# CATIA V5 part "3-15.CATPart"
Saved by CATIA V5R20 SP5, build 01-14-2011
Part number: Part3
Material "Brass": density 8216 kg/m3, Young's modulus 1.31e+11 Pa, Poisson ratio 0.35, thermal expansion 1.67e-05 1/K
Bounding box of the stored display mesh (mm): x -25 to 25, y -25 to 25, z -60 to 50
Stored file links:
  E:\180511232\3-15.CATPart
  C:\Program Files\Dassault Systemes\B20\intel_a\startup\materials\Catalog.CATMaterial
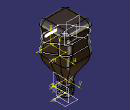
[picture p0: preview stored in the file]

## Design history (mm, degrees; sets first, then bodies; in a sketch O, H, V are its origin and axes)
Set1
  Sketch1 on xy-plane, origin (0, 0, 0), H (1, 0, 0), V (0, 1, 0)
    line L1 (25, 25) -> (25, -25)
    line L2 (25, -25) -> (-25, -25)
    line L3 (-25, -25) -> (-25, 25)
    line L4 (-25, 25) -> (25, 25)
    length L4 = 50
    length L1 = 50
    vertical: L1 V, L3 V
    horizontal: L2 H, L4 H
    equidistance: L1 L3 O, L2 L4 O
  Sketch2 on face of Pad1 from Sketch1.L3, origin (-25, 0, 0), H (0, -1, 0), V (0, 0, 1)
    spline S1 through (-42.1157, 18.4827) (-11.1794, 31.201) (8.2754, 22.6162) (38.5738, 31.201)
  Extrude1: Element1 Sketch2, Lim1 53, Lim2 53
  MultiSel1: CommonCtxFeats ({extract ExtractElem face of Pad1 from Sketch1.L3}; {extract ExtractElem face of Fillet1}; {extract ExtractElem face of Pad1 from Sketch1.L4}; {extract ExtractElem face of Fillet1}; {extract ExtractElem face of Pad1 from Sketch1.L1}; {extract ExtractElem face of Fillet1}; {extract ExtractElem face of Pad1 from Sketch1.L2}; {extract ExtractElem face of Fillet1})
  Sketch3 on face of Pad1 from Sketch1.L1, origin (25, 0, 0), H (0, 1, 0), V (0, 0, 1)
    spline S1 through (-35.6508, 14.5425) (-12.1043, 6.1379) (11.1515, 14.5425) (28.8841, 14.5425)
  Extrude2: Element1 Sketch3, Lim1 65, Lim2 65
  MultiSel2: CommonCtxFeats ({extract ExtractElem face of Pad1 from Sketch1.L1}; {extract ExtractElem face of Fillet1}; {extract ExtractElem face of Pad1 from Sketch1.L2}; {extract ExtractElem face of Fillet1}; {extract ExtractElem face of Pad1 from Sketch1.L3}; {extract ExtractElem face of Fillet1}; {extract ExtractElem face of Pad1 from Sketch1.L4}; {extract ExtractElem face of Fillet1})
  Join1: Elements ({intersect ToIntersect1 {extract ExtractElem face of Fillet1}, ToIntersect2 Extrude1}; {intersect ToIntersect1 {extract ExtractElem face of Pad1 from Sketch1.L4}, ToIntersect2 Extrude1}; {intersect ToIntersect1 {extract ExtractElem face of Fillet1}, ToIntersect2 Extrude1}; {intersect ToIntersect1 {extract ExtractElem face of Pad1 from Sketch1.L1}, ToIntersect2 Extrude1}; {intersect ToIntersect1 {extract ExtractElem face of Fillet1}, ToIntersect2 Extrude1}; {intersect ToIntersect1 {extract ExtractElem face of Pad1 from Sketch1.L2}, ToIntersect2 Extrude1}; {intersect ToIntersect1 {extract ExtractElem face of Fillet1}, ToIntersect2 Extrude1}; {intersect ToIntersect1 {extract ExtractElem face of Pad1 from Sketch1.L3}, ToIntersect2 Extrude1})
  Plane1: type OffsetPt, RefPlane face of Pad1 from Sketch1.L2, RefPoint vertex of MultiSel2
  Circle1: type CtrRad, Start 0, End 180, Center vertex of MultiSel2, Support Plane1, Radius 1, FirstDirection (-1, 0, 0)
  Plane2: type OffsetPt, RefPlane face of Pad1 from Sketch1.L2, RefPoint vertex [face of MultiSel1 | face of MultiSel1]
  Circle2: type CtrRad, Start 0, End 180, Center vertex [face of MultiSel1 | face of MultiSel1], Support Plane2, Radius 1, FirstDirection (-1, 0, 0)
Body1 (main body), material "Brass"
  Pad1: profile Sketch1, direction (0, 0, 1), length 50
  Fillet1: on edge [face of Pad1 from Sketch1.L4 | face of Pad1 from Sketch1.L1]; edge [face of Pad1 from Sketch1.L3 | face of Pad1 from Sketch1.L4]; edge [face of Pad1 from Sketch1.L1 | face of Pad1 from Sketch1.L2]; edge [face of Pad1 from Sketch1.L2 | face of Pad1 from Sketch1.L3]
  Fillet2: radius 8, on end face of Pad1
  Plane3: type Offset, RefPlane xy-plane, Offset 40, reversed
  Sketch4 on Plane3, origin (0, 0, -40), H (1, 0, 0), V (0, 1, 0)
  Sketch5 on Plane3, origin (0, 0, -40), H (1, 0, 0), V (0, 1, 0)
    circle A1 centre (0, 0) radius 10
    radius A1 = 10
  Sketch6 on start face of Pad1, origin (0, 0, 0), H (1, 0, 0), V (0, -1, 0)
    reference projected line E1 (-25, -25) -> (-25, 25) from edge [start face of Pad1 | face of Pad1 from Sketch1.L3]
    distance E1 O = 25
  Pad2: profile Sketch5, direction (0, 0, -1), length 20
  Sketch7 on start face of Pad1, origin (0, 0, 0), H (1, 0, 0), V (0, -1, 0)
    point P1 (25, 0)
    distance P1 O = 25
    coincidence: P1 H
  Sketch8 on Plane3, origin (0, 0, -40), H (1, 0, 0), V (0, 1, 0)
    point P1 (25, 0)
    distance P1 O = 25
    coincidence: P1 H
  Sketch9 on start face of Pad2, origin (0, 0, -40), H (1, 0, 0), V (0, 1, 0)
    point P1 (10, 0)
    distance P1 O = 10
    coincidence: P1 H
  Loft1: solid, Sections ({boundary Boundary {extract ExtractElem start face of Pad2}}; {boundary Boundary {extract ExtractElem start face of Pad1}}), StartFace start face of Pad2, EndFace start face of Pad1
  Slot1: profile Circle1, centre curve {join Elements ({intersect ToIntersect2 Extrude2}; {intersect ToIntersect2 Extrude2}; {intersect ToIntersect2 Extrude2}; {intersect ToIntersect2 Extrude2}; {intersect ToIntersect2 Extrude2}; {intersect ToIntersect2 Extrude2}; {intersect ToIntersect2 Extrude2}; {intersect ToIntersect2 Extrude2})}
  Slot2: profile Circle2, centre curve {join Elements ({intersect ToIntersect2 Extrude1}; {intersect ToIntersect2 Extrude1}; {intersect ToIntersect2 Extrude1}; {intersect ToIntersect2 Extrude1}; {intersect ToIntersect2 Extrude1}; {intersect ToIntersect2 Extrude1}; {intersect ToIntersect2 Extrude1}; {intersect ToIntersect2 Extrude1})}
  Shell1: ExtOffset 0, Face end face of Pad2, IntOffset 2
  Plane4: type OffsetPt, RefPlane yz-plane, RefPoint Sketch9
  Sketch10 on Plane4, origin (10, 0, 0), H (0, 1, 0), V (0, 0, 1)
    point P1 (0, -60)
    reference projected point E1 (0, -40) from Sketch9
    point P2 (0, -56.5)
    point P3 (0, -43.5)
    reference projected point E2 (0, -40) from Sketch9
    distance P1 E1 = 20
    distance P2 P1 = 3.5
    distance P3 E2 = 3.5
    coincidence: P1 V, P2 V, P3 V
  AxisLine1: Element face of Shell1
  Helix1: Direction AxisLine1, RefPoint Sketch10.P2, Pitch 1.5, Height 13, TaperAngle 0
  Loft2: solid, Sections ({boundary Boundary {extract ExtractElem start face of Pad2}}; {boundary Boundary {extract ExtractElem start face of Pad1}}), StartFace start face of Pad2, EndFace start face of Pad1
Body2
  Sketch11 on face of Pad1 from Sketch1.L2, origin (0, -25, 0), H (1, 0, 0), V (0, 0, 1)
    point P1 (-30.2053, 2.346)
    construction line L1 through (42.0975, -13.7551) direction (1, 0)
    construction line L2 through (86.6764, -29.8072) direction (0, 1)
    construction line L3 through (29.5005, 2.9963) direction (1, 0)
    construction line L4 through (29.5005, 2.9963) direction (0, 1)
    point P2 (11.3773, 4.4039)
    point P3 (-0.4552, 16.4417)
    polyline C1
    polyline C2
    polyline C3
    polyline C4
    polyline C5
    polyline C6
    polyline C7
    polyline C8
    polyline C9
    polyline C10
    polyline C11
    polyline C12
    polyline C13
  Point1: type OnCurve, Support Helix1, RefPoint vertex of Helix1, Length -10
  Line1: type Normal, RefPoint vertex of Helix1, RefSkin face of Pad2 from Sketch5.A1, Start 0, End 5
  Connect1: Curve1 Line1, Point1 vertex of Line1, Tension1 1.2, Curve2 Helix1, Point2 Point1, Tension2 1
  Point2: type OnCurve, Support Connect1, RefPoint Sketch10.P2, Length 10
  Point3: type OnCurve, Support Connect1, RefPoint Sketch10.P2, Length 10
  Line2: type Normal, RefPoint Sketch10.P2, RefSkin face of Pad2 from Sketch5.A1, Start 0, End 5
  Connect2: Curve1 Line2, Point1 vertex of Line2, Tension1 1, Curve2 Connect1, Point2 Point2, Tension2 1
  Plane5: type OffsetPt, RefPlane Plane4, RefPoint vertex of Connect2
  Sketch12 on Plane5, origin (5, 0, 0), H (0, 1, 0), V (0, 0, 1)
    circle A1 centre (0, -56.5418) radius 0.75
    point P1 (0, -56.5418)
    radius A1 = 0.75
    coincidence: P1 V
  Rib1: profile Sketch12, centre curve Connect2
  Plane6: type Offset, RefPlane end face of Pad2, Offset 10, reversed
  Sketch13 on end face of Pad2, origin (0, 0, -60), H (1, 0, 0), V (0, -1, 0)
    reference projected circle E1 centre (0, 0) radius 8 from edge [face of Shell1 | end face of Pad2]
    radius E1 = 8 (reference)
  Body3
    Sketch14 on Plane6, origin (0, 0, -70), H (1, 0, 0), V (0, 1, 0)
      circle A1 centre (0, 0) radius 8
      radius A1 = 8
    Pad3: profile Sketch14, direction (0, 0, 1), length 40
  Remove1: tool Body3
